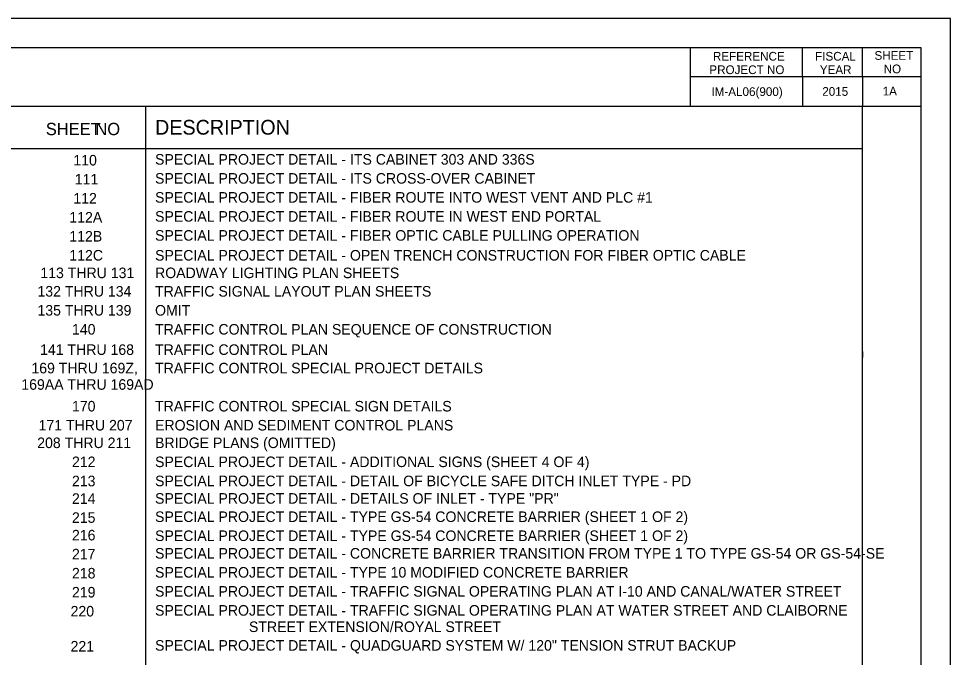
# Model space of a CAD drawing. Extents: x -12822 to 16384, y -6351 to 1913.
# Drawn here: x 54 to 850, y 1337 to 1882 of the extents above; entities that cross this region are included whole.
import ezdxf

# ---------------------------------------------------------------- set-up
doc = ezdxf.new("R2010")
doc.units = 0
for name, color, linetype in [('2', 7, 'Continuous'), ('ANNO-SHT', 7, 'Continuous'), ('Level 1', 7, 'Continuous'), ('Level 10', 7, 'Continuous'), ('Level 6', 7, 'Continuous'), ('Level 62', 7, 'Continuous'), ('SHT-BDR', 7, 'Continuous'), ('SHT-BNDRY', 7, 'Continuous')]:
    doc.layers.add(name, color=color, linetype=linetype)

msp = doc.modelspace()

# ---------------------------------------------------------------- linework, layer by layer
at = {"layer": '2'}
msp.add_lwpolyline([(774.79, 1598.01), (774.84, 1593.01)], dxfattribs=at)
msp.add_lwpolyline([(774.79, 1598.01), (774.84, 1593.01)], dxfattribs=at)
at = {"layer": 'Level 1'}
for p, q in [((162.57, 857.3), (162.57, 1807.3)), ((-725.04, 1771.3), (774.96, 1771.3))]:
    msp.add_line(p, q, dxfattribs=at)
at = {"layer": 'Level 6'}
for p, q in [((627.69, 1857.25), (627.69, 1807.3)), ((723.51, 1832.26), (723.51, 1857.26)), ((774.96, 1832.91), (774.96, 1857.26)), ((824.98, 1832.56), (627.69, 1832.56)), ((723.51, 1832.26), (723.51, 1807.3)), ((774.96, 1832.91), (774.96, 1807.3)), ((824.98, 1807.3), (633.75, 1807.3))]:
    msp.add_line(p, q, dxfattribs=at)
at = {"layer": 'Level 62'}
msp.add_lwpolyline([(-850.02, 782.25), (849.98, 782.25), (849.98, 1882.25), (-850.02, 1882.25)], close=True, dxfattribs=at)
at = {"layer": 'SHT-BDR'}
msp.add_lwpolyline([(-725.04, 857.3), (774.96, 857.3), (774.96, 1807.3), (-725.04, 1807.3)], close=True, dxfattribs=at)
at = {"layer": 'SHT-BNDRY'}
msp.add_lwpolyline([(-787.52, 807.25), (824.98, 807.25), (824.98, 1857.25), (-787.52, 1857.25)], close=True, dxfattribs=at)

# ---------------------------------------------------------------- texts
at = {"layer": 'ANNO-SHT'}
for s, height, p in [('IM-AL06(900)', 7.4493, (645.83, 1816.21)), ('2015', 7.449, (740.51, 1816.36)), (' 1A ', 7.449, (789.36, 1816.66))]:
    msp.add_text(s, height=height, dxfattribs=at).set_placement(p)
at = {"layer": 'Level 10'}
for s, height, p in [('SHEET', 10.5, (77.12, 1782.79)), (' NO', 10.5, (115.59, 1782.79)), ('DESCRIPTION', 12.6, (170.44, 1783.21)), ('110', 9, (100.64, 1756.88)), ('SPECIAL PROJECT DETAIL - ITS CABINET 303 AND 336S', 9, (170.44, 1757.61)), ('111', 9, (101.83, 1740.65)), ('SPECIAL PROJECT DETAIL - ITS CROSS-OVER CABINET ', 9, (170.44, 1741.38)), ('112', 9, (100.64, 1724.41)), ('SPECIAL PROJECT DETAIL - FIBER ROUTE INTO WEST VENT AND PLC #1', 9, (170.44, 1725.14)), ('112A', 9, (97.21, 1708.17)), ('SPECIAL PROJECT DETAIL - FIBER ROUTE IN WEST END PORTAL', 9, (170.44, 1708.9)), ('112B', 9, (97.21, 1691.94)), ('SPECIAL PROJECT DETAIL - FIBER OPTIC CABLE PULLING OPERATION', 9, (170.44, 1692.67)), ('112C', 9, (97.21, 1675.7)), ('SPECIAL PROJECT DETAIL - OPEN TRENCH CONSTRUCTION FOR FIBER OPTIC CABLE', 9, (170.44, 1675.7)), ('113 THRU 131', 9, (72.43, 1660.69)), ('ROADWAY LIGHTING PLAN SHEETS', 9, (170.44, 1660.69)), ('132 THRU 134', 9, (69.95, 1644.95)), ('TRAFFIC SIGNAL LAYOUT PLAN SHEETS', 9, (170.44, 1644.95)), ('135 THRU 139', 9, (69.95, 1628.72)), ('OMIT', 9, (170.44, 1628.72)), ('140', 9, (99.45, 1612.48)), ('TRAFFIC CONTROL PLAN SEQUENCE OF CONSTRUCTION', 9, (170.44, 1612.48)), ('141 THRU 168', 9, (72.19, 1595.16)), ('TRAFFIC CONTROL PLAN', 9, (170.44, 1595.16)), ('169 THRU 169Z,', 9, (64.77, 1579.38)), ('TRAFFIC CONTROL SPECIAL PROJECT DETAILS', 9, (170.44, 1579.38)), ('169AA THRU 169AD', 9, (56.16, 1565.38)), ('170', 9, (99.45, 1546.84)), ('TRAFFIC CONTROL SPECIAL SIGN DETAILS', 9, (170.44, 1546.84)), ('171 THRU 207', 9, (70.93, 1530.6)), ('EROSION AND SEDIMENT CONTROL PLANS', 9, (170.44, 1530.6)), ('208 THRU 211', 9, (69.74, 1515.59)), ('BRIDGE PLANS (OMITTED)', 9, (170.44, 1515.59)), ('212', 9, (99.45, 1499.36)), ('SPECIAL PROJECT DETAIL - ADDITIONAL SIGNS (SHEET 4 OF 4)', 9, (170.44, 1499.36)), ('213', 9, (99.45, 1482.99)), ('SPECIAL PROJECT DETAIL - DETAIL OF BICYCLE SAFE DITCH INLET TYPE - PD', 9, (170.44, 1483.05)), ('214', 9, (99.45, 1467.98)), ('SPECIAL PROJECT DETAIL - DETAILS OF INLET - TYPE "PR"', 9, (170.44, 1468.1)), ('215', 9, (99.45, 1451.75)), ('SPECIAL PROJECT DETAIL - TYPE GS-54 CONCRETE BARRIER (SHEET 1 OF 2)', 9, (170.44, 1452.48)), ('216', 9, (99.45, 1436.74)), ('SPECIAL PROJECT DETAIL - TYPE GS-54 CONCRETE BARRIER (SHEET 1 OF 2)', 9, (170.44, 1436.24)), ('217', 9, (99.45, 1420.56)), ('SPECIAL PROJECT DETAIL - CONCRETE BARRIER TRANSITION FROM TYPE 1 TO TYPE GS-54 OR GS-54-SE', 9, (170.44, 1421.23)), ('218', 9, (99.45, 1404.27)), ('SPECIAL PROJECT DETAIL - TYPE 10 MODIFIED CONCRETE BARRIER', 9, (170.44, 1405)), ('219', 9, (99.45, 1388.03)), ('SPECIAL PROJECT DETAIL - TRAFFIC SIGNAL OPERATING PLAN AT I-10 AND CANAL/WATER STREET', 9, (170.44, 1388.76)), ('220', 9, (98.26, 1371.79)), ('SPECIAL PROJECT DETAIL - TRAFFIC SIGNAL OPERATING PLAN AT WATER STREET AND CLAIBORNE', 9, (170.44, 1372.52)), ('                        STREET EXTENSION/ROYAL STREET', 9, (170.44, 1358.52)), ('221', 9, (98.26, 1341.89)), ('SPECIAL PROJECT DETAIL - QUADGUARD SYSTEM W/ 120" TENSION STRUT BACKUP', 9, (170.44, 1342.62))]:
    msp.add_text(s, height=height, dxfattribs=at).set_placement(p)
at = {"layer": 'Level 6'}
for s, p in [('REFERENCE', (647.06, 1846.41)), ('FISCAL', (734.41, 1846.41)), ('SHEET', (785.15, 1847.11)), ('PROJECT NO', (644.06, 1834.91)), ('YEAR', (738.41, 1834.91)), ('NO', (792.99, 1835.61))]:
    msp.add_text(s, height=7.441, dxfattribs=at).set_placement(p)

doc.saveas('drawing.dxf')
